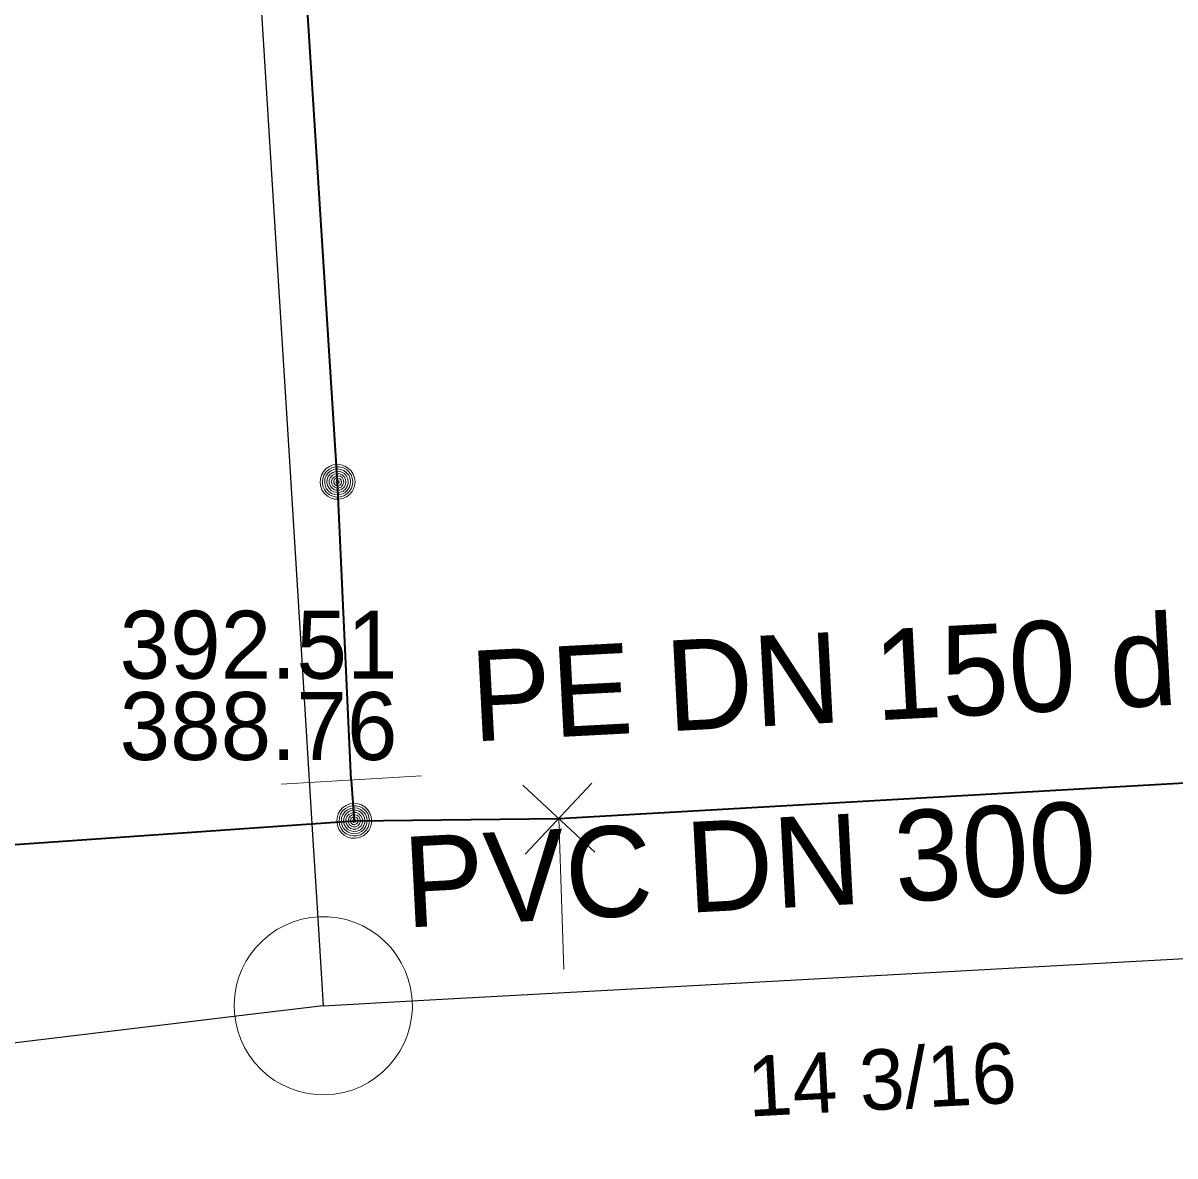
# Model space of a CAD drawing. Extents: x -772952 to -772403, y -1033777 to -1033210.
# Drawn here: x -772638.21 to -772622.94, y -1033348.28 to -1033333.27 of the extents above; entities that cross this region are included whole.
import ezdxf

# ---------------------------------------------------------------- set-up
doc = ezdxf.new("R2010")
doc.units = 0
doc.header["$LTSCALE"] = 0.36
for name, color, linetype, lineweight in [('15', 7, 'Continuous', 13), ('16', 7, 'Continuous', 35), ('2', 7, 'Continuous', 25), ('4', 7, 'Continuous', 13), ('59', 7, 'Continuous', 13)]:
    doc.layers.add(name, color=color, linetype=linetype, lineweight=lineweight)
for name, color, linetype in [('17', 7, 'Continuous'), ('3', 7, 'Continuous'), ('6', 7, 'Continuous')]:
    doc.layers.add(name, color=color, linetype=linetype)

msp = doc.modelspace()

# ---------------------------------------------------------------- linework, layer by layer
at = {"layer": '15'}
for p, q in [((-772634.788, -1033343.355), (-772632.93, -1033343.244)), ((-772630.669, -1033343.34), (-772631.553, -1033344.28)), ((-772631.584, -1033343.366), (-772630.633, -1033344.255))]:
    msp.add_line(p, q, dxfattribs=at)
for points in [[(-772633.809, -1033339.35), (-772633.815, -1033339.298), (-772633.832, -1033339.248), (-772633.861, -1033339.204), (-772633.898, -1033339.167), (-772633.943, -1033339.14), (-772633.993, -1033339.123), (-772634.046, -1033339.119), (-772634.098, -1033339.126), (-772634.147, -1033339.145), (-772634.19, -1033339.174), (-772634.226, -1033339.213), (-772634.252, -1033339.258), (-772634.268, -1033339.309), (-772634.271, -1033339.361), (-772634.263, -1033339.413), (-772634.243, -1033339.462), (-772634.212, -1033339.505), (-772634.173, -1033339.539), (-772634.127, -1033339.565), (-772634.076, -1033339.579), (-772634.023, -1033339.581), (-772633.972, -1033339.571), (-772633.924, -1033339.55), (-772633.881, -1033339.519), (-772633.847, -1033339.478), (-772633.823, -1033339.432), (-772633.811, -1033339.381)], [(-772633.839, -1033339.35), (-772633.845, -1033339.301), (-772633.862, -1033339.255), (-772633.89, -1033339.215), (-772633.927, -1033339.183), (-772633.971, -1033339.161), (-772634.019, -1033339.15), (-772634.068, -1033339.15), (-772634.115, -1033339.163), (-772634.158, -1033339.187), (-772634.194, -1033339.22), (-772634.221, -1033339.261), (-772634.237, -1033339.308), (-772634.241, -1033339.357), (-772634.234, -1033339.405), (-772634.215, -1033339.45), (-772634.185, -1033339.49), (-772634.147, -1033339.521), (-772634.103, -1033339.541), (-772634.055, -1033339.551), (-772634.006, -1033339.549), (-772633.959, -1033339.534), (-772633.916, -1033339.509), (-772633.882, -1033339.475), (-772633.856, -1033339.433), (-772633.842, -1033339.386)], [(-772633.869, -1033339.35), (-772633.875, -1033339.305), (-772633.892, -1033339.263), (-772633.92, -1033339.228), (-772633.956, -1033339.201), (-772633.998, -1033339.184), (-772634.043, -1033339.179), (-772634.088, -1033339.185), (-772634.129, -1033339.204), (-772634.164, -1033339.232), (-772634.191, -1033339.269), (-772634.207, -1033339.311), (-772634.211, -1033339.356), (-772634.204, -1033339.401), (-772634.185, -1033339.442), (-772634.156, -1033339.476), (-772634.119, -1033339.502), (-772634.076, -1033339.518), (-772634.031, -1033339.521), (-772633.986, -1033339.513), (-772633.946, -1033339.493), (-772633.912, -1033339.464), (-772633.886, -1033339.426), (-772633.872, -1033339.383)], [(-772633.899, -1033339.35), (-772633.904, -1033339.309), (-772633.922, -1033339.272), (-772633.949, -1033339.241), (-772633.984, -1033339.22), (-772634.024, -1033339.209), (-772634.065, -1033339.211), (-772634.104, -1033339.224), (-772634.138, -1033339.248), (-772634.163, -1033339.28), (-772634.178, -1033339.318), (-772634.181, -1033339.359), (-772634.173, -1033339.399), (-772634.153, -1033339.435), (-772634.124, -1033339.464), (-772634.087, -1033339.483), (-772634.047, -1033339.491), (-772634.006, -1033339.487), (-772633.968, -1033339.472), (-772633.936, -1033339.446), (-772633.913, -1033339.412), (-772633.9, -1033339.373)], [(-772633.929, -1033339.35), (-772633.934, -1033339.314), (-772633.952, -1033339.282), (-772633.978, -1033339.257), (-772634.012, -1033339.242), (-772634.048, -1033339.239), (-772634.083, -1033339.247), (-772634.114, -1033339.267), (-772634.137, -1033339.295), (-772634.15, -1033339.329), (-772634.15, -1033339.366), (-772634.139, -1033339.401), (-772634.118, -1033339.43), (-772634.088, -1033339.451), (-772634.053, -1033339.461), (-772634.016, -1033339.459), (-772633.982, -1033339.445), (-772633.955, -1033339.422), (-772633.936, -1033339.39), (-772633.929, -1033339.355)], [(-772633.959, -1033339.35), (-772633.964, -1033339.319), (-772633.981, -1033339.293), (-772634.007, -1033339.276), (-772634.037, -1033339.269), (-772634.068, -1033339.273), (-772634.095, -1033339.29), (-772634.113, -1033339.314), (-772634.121, -1033339.345), (-772634.117, -1033339.375), (-772634.102, -1033339.403), (-772634.078, -1033339.422), (-772634.048, -1033339.431), (-772634.017, -1033339.428), (-772633.989, -1033339.414), (-772633.969, -1033339.39), (-772633.959, -1033339.361)], [(-772633.989, -1033339.35), (-772633.994, -1033339.326), (-772634.011, -1033339.308), (-772634.034, -1033339.299), (-772634.058, -1033339.302), (-772634.079, -1033339.316), (-772634.09, -1033339.338), (-772634.09, -1033339.363), (-772634.078, -1033339.384), (-772634.058, -1033339.398), (-772634.033, -1033339.401), (-772634.01, -1033339.392), (-772633.994, -1033339.374)], [(-772634.019, -1033339.35), (-772634.024, -1033339.335), (-772634.039, -1033339.329), (-772634.054, -1033339.333), (-772634.061, -1033339.347), (-772634.057, -1033339.362), (-772634.044, -1033339.371), (-772634.029, -1033339.368), (-772634.019, -1033339.356)], [(-772633.588, -1033343.84), (-772633.594, -1033343.788), (-772633.611, -1033343.738), (-772633.64, -1033343.694), (-772633.677, -1033343.657), (-772633.722, -1033343.63), (-772633.772, -1033343.613), (-772633.825, -1033343.609), (-772633.877, -1033343.616), (-772633.926, -1033343.635), (-772633.969, -1033343.664), (-772634.005, -1033343.703), (-772634.031, -1033343.748), (-772634.047, -1033343.799), (-772634.05, -1033343.851), (-772634.042, -1033343.903), (-772634.022, -1033343.952), (-772633.991, -1033343.995), (-772633.952, -1033344.029), (-772633.906, -1033344.055), (-772633.855, -1033344.069), (-772633.802, -1033344.071), (-772633.751, -1033344.061), (-772633.703, -1033344.04), (-772633.66, -1033344.009), (-772633.626, -1033343.968), (-772633.602, -1033343.922), (-772633.59, -1033343.871)], [(-772633.618, -1033343.84), (-772633.624, -1033343.791), (-772633.641, -1033343.745), (-772633.669, -1033343.705), (-772633.706, -1033343.673), (-772633.75, -1033343.651), (-772633.798, -1033343.64), (-772633.847, -1033343.64), (-772633.894, -1033343.653), (-772633.937, -1033343.677), (-772633.973, -1033343.71), (-772634, -1033343.751), (-772634.016, -1033343.798), (-772634.02, -1033343.847), (-772634.013, -1033343.895), (-772633.994, -1033343.94), (-772633.964, -1033343.98), (-772633.926, -1033344.011), (-772633.882, -1033344.031), (-772633.834, -1033344.041), (-772633.785, -1033344.039), (-772633.738, -1033344.024), (-772633.695, -1033343.999), (-772633.661, -1033343.965), (-772633.635, -1033343.923), (-772633.621, -1033343.876)], [(-772633.648, -1033343.84), (-772633.654, -1033343.795), (-772633.671, -1033343.753), (-772633.699, -1033343.718), (-772633.735, -1033343.691), (-772633.777, -1033343.674), (-772633.822, -1033343.669), (-772633.867, -1033343.675), (-772633.908, -1033343.694), (-772633.943, -1033343.722), (-772633.97, -1033343.759), (-772633.986, -1033343.801), (-772633.99, -1033343.846), (-772633.983, -1033343.891), (-772633.964, -1033343.932), (-772633.935, -1033343.966), (-772633.898, -1033343.992), (-772633.855, -1033344.008), (-772633.81, -1033344.011), (-772633.765, -1033344.003), (-772633.725, -1033343.983), (-772633.691, -1033343.954), (-772633.665, -1033343.916), (-772633.651, -1033343.873)], [(-772633.678, -1033343.84), (-772633.683, -1033343.799), (-772633.701, -1033343.762), (-772633.728, -1033343.731), (-772633.763, -1033343.71), (-772633.803, -1033343.699), (-772633.844, -1033343.701), (-772633.883, -1033343.714), (-772633.917, -1033343.738), (-772633.942, -1033343.77), (-772633.957, -1033343.808), (-772633.96, -1033343.849), (-772633.952, -1033343.889), (-772633.932, -1033343.925), (-772633.903, -1033343.954), (-772633.866, -1033343.973), (-772633.826, -1033343.981), (-772633.785, -1033343.977), (-772633.747, -1033343.962), (-772633.715, -1033343.936), (-772633.692, -1033343.902), (-772633.679, -1033343.863)], [(-772633.708, -1033343.84), (-772633.713, -1033343.804), (-772633.731, -1033343.772), (-772633.757, -1033343.747), (-772633.791, -1033343.732), (-772633.827, -1033343.729), (-772633.862, -1033343.737), (-772633.893, -1033343.757), (-772633.916, -1033343.785), (-772633.929, -1033343.819), (-772633.929, -1033343.856), (-772633.918, -1033343.891), (-772633.897, -1033343.92), (-772633.867, -1033343.941), (-772633.832, -1033343.951), (-772633.795, -1033343.949), (-772633.761, -1033343.935), (-772633.734, -1033343.912), (-772633.715, -1033343.88), (-772633.708, -1033343.845)], [(-772633.738, -1033343.84), (-772633.743, -1033343.809), (-772633.76, -1033343.783), (-772633.786, -1033343.766), (-772633.816, -1033343.759), (-772633.847, -1033343.763), (-772633.874, -1033343.78), (-772633.892, -1033343.804), (-772633.9, -1033343.835), (-772633.896, -1033343.865), (-772633.881, -1033343.893), (-772633.857, -1033343.912), (-772633.827, -1033343.921), (-772633.796, -1033343.918), (-772633.768, -1033343.904), (-772633.748, -1033343.88), (-772633.738, -1033343.851)], [(-772633.768, -1033343.84), (-772633.773, -1033343.816), (-772633.79, -1033343.798), (-772633.813, -1033343.789), (-772633.837, -1033343.792), (-772633.858, -1033343.806), (-772633.869, -1033343.828), (-772633.869, -1033343.853), (-772633.857, -1033343.874), (-772633.837, -1033343.888), (-772633.812, -1033343.891), (-772633.789, -1033343.882), (-772633.773, -1033343.864)], [(-772633.798, -1033343.84), (-772633.803, -1033343.825), (-772633.818, -1033343.819), (-772633.833, -1033343.823), (-772633.84, -1033343.837), (-772633.836, -1033343.852), (-772633.823, -1033343.861), (-772633.808, -1033343.858), (-772633.798, -1033343.846)]]:
    msp.add_lwpolyline(points, close=True, dxfattribs=at)
at = {"layer": '16'}
for q in [(-772634.04, -1033339.35), (-772633.819, -1033343.84)]:
    msp.add_line((-772633.86, -1033343.3), q, dxfattribs=at)
for points in [[(-772634.039, -1033339.35), (-772636.721, -1033297.19), (-772638.259, -1033272.415), (-772638.554, -1033267.657), (-772644.984, -1033243.6), (-772656.572, -1033209.741)], [(-772633.819, -1033343.84), (-772631.109, -1033343.809), (-772620.26, -1033343.19), (-772612.6, -1033342.82)], [(-772678.01, -1033345.53), (-772670.23, -1033345.28), (-772667.19, -1033345.359), (-772652.429, -1033345.14), (-772633.819, -1033343.84)]]:
    msp.add_lwpolyline(points, dxfattribs=at)
at = {"layer": '2'}
for points in [[(-772636.688, -1033306.747), (-772636.614, -1033307.94), (-772636.564, -1033308.736), (-772636.377, -1033311.752), (-772636.243, -1033313.906), (-772636.075, -1033316.603), (-772635.893, -1033319.538), (-772635.727, -1033322.199), (-772635.564, -1033324.827), (-772635.404, -1033327.402), (-772635.208, -1033330.553), (-772635.061, -1033332.92), (-772634.871, -1033335.979), (-772634.7, -1033338.723), (-772634.523, -1033341.569), (-772634.366, -1033344.097), (-772634.315, -1033344.918), (-772634.274, -1033345.566), (-772634.23, -1033346.29)], [(-772634.23, -1033346.29), (-772633.68, -1033346.26), (-772633.531, -1033346.251), (-772632.819, -1033346.212), (-772629.247, -1033346.017), (-772625.786, -1033345.828), (-772624.992, -1033345.785), (-772621.84, -1033345.613), (-772621.027, -1033345.568), (-772620.529, -1033345.541), (-772619.95, -1033345.51)], [(-772634.23, -1033346.29), (-772635.232, -1033346.41), (-772636.035, -1033346.507), (-772638.931, -1033346.857), (-772642.03, -1033347.23), (-772644.969, -1033347.585), (-772649.229, -1033348.099), (-772649.71, -1033348.157), (-772650.097, -1033348.203), (-772650.73, -1033348.28)]]:
    msp.add_lwpolyline(points, dxfattribs=at)
at = {"layer": '4'}
msp.add_lwpolyline([(-772633.049, -1033346.29), (-772633.056, -1033346.171), (-772633.074, -1033346.054), (-772633.103, -1033345.938), (-772633.144, -1033345.827), (-772633.196, -1033345.72), (-772633.259, -1033345.619), (-772633.331, -1033345.524), (-772633.413, -1033345.438), (-772633.503, -1033345.36), (-772633.601, -1033345.291), (-772633.704, -1033345.233), (-772633.813, -1033345.186), (-772633.927, -1033345.149), (-772634.043, -1033345.124), (-772634.161, -1033345.112), (-772634.28, -1033345.111), (-772634.399, -1033345.122), (-772634.515, -1033345.145), (-772634.629, -1033345.179), (-772634.739, -1033345.225), (-772634.843, -1033345.282), (-772634.942, -1033345.349), (-772635.032, -1033345.425), (-772635.116, -1033345.51), (-772635.19, -1033345.604), (-772635.254, -1033345.704), (-772635.308, -1033345.81), (-772635.351, -1033345.921), (-772635.383, -1033346.035), (-772635.402, -1033346.153), (-772635.41, -1033346.272), (-772635.406, -1033346.39), (-772635.39, -1033346.508), (-772635.362, -1033346.624), (-772635.323, -1033346.736), (-772635.272, -1033346.844), (-772635.211, -1033346.946), (-772635.14, -1033347.042), (-772635.059, -1033347.129), (-772634.971, -1033347.209), (-772634.875, -1033347.279), (-772634.772, -1033347.339), (-772634.664, -1033347.388), (-772634.551, -1033347.426), (-772634.434, -1033347.452), (-772634.317, -1033347.467), (-772634.198, -1033347.47), (-772634.08, -1033347.461), (-772633.962, -1033347.44), (-772633.848, -1033347.407), (-772633.738, -1033347.363), (-772633.632, -1033347.308), (-772633.532, -1033347.242), (-772633.44, -1033347.167), (-772633.356, -1033347.083), (-772633.281, -1033346.991), (-772633.215, -1033346.892), (-772633.159, -1033346.787), (-772633.115, -1033346.677), (-772633.081, -1033346.563), (-772633.059, -1033346.446), (-772633.049, -1033346.327)], close=True, dxfattribs=at)
at = {"layer": '59'}
msp.add_line((-772631.109, -1033343.809), (-772631.041, -1033345.809), dxfattribs=at)

# ---------------------------------------------------------------- texts
at = {"layer": '17'}
msp.add_text('PE DN 150 d 160 ', height=1.2, rotation=3, dxfattribs=at).set_placement((-772632.245, -1033342.79))
at = {"layer": '3'}
for s, height, p in [('PVC DN 300', 1.2, (-772633.135, -1033345.255)), ('14 3/16', 0.8, (-772628.59, -1033347.759))]:
    msp.add_text(s, height=height, rotation=3, dxfattribs=at).set_placement(p)
at = {"layer": '6'}
for s, p in [('392.51', (-772636.928, -1033341.957)), ('388.76', (-772636.928, -1033343.034))]:
    msp.add_text(s, height=0.9, dxfattribs=at).set_placement(p)

doc.saveas('drawing.dxf')
